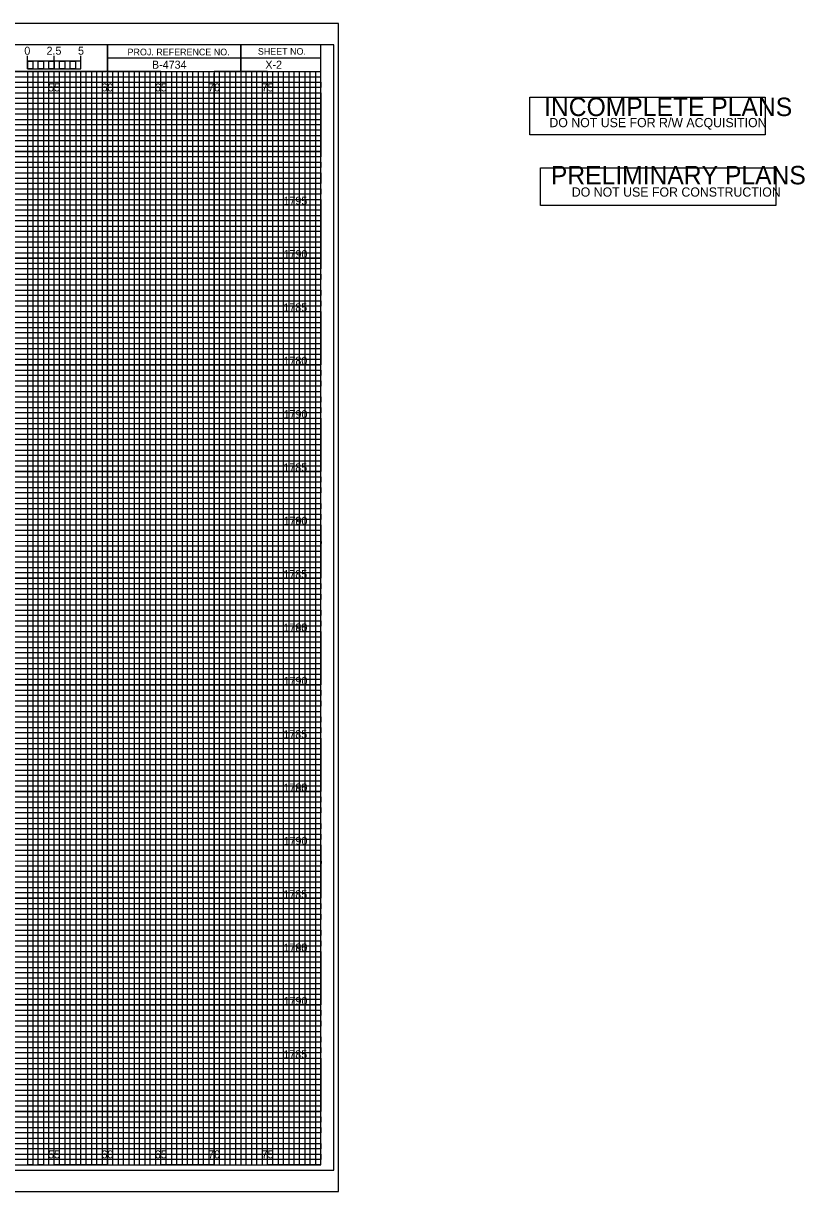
# Model space of a CAD drawing. Extents: x -7 to 205, y -2 to 107.
# Drawn here: x 132.1 to 205.3, y -2.5 to 107 of the extents above; entities that cross this region are included whole.
import ezdxf

# ---------------------------------------------------------------- set-up
doc = ezdxf.new("R2010")
doc.units = 0
for name, color, linetype in [('Prop XS Bar Scale Labels', 7, 'Continuous'), ('Prop XS Elevation Labels', 7, 'Continuous'), ('Prop XS Offset Labels', 7, 'Continuous'), ('Prop XS Project Number', 7, 'Continuous'), ('Prop XS Sheet Number', 7, 'Continuous'), ('Sheet Cross Section CELL', 7, 'Continuous'), ('Sheet Cross Section Grid Major CELL', 7, 'Continuous'), ('Sheet Cross Section Grid Middle CELL', 7, 'Continuous'), ('Sheet Cross Section Grid Minor 1 CELL', 7, 'Continuous'), ('Sheet Cross Section Grid Minor 2 CELL', 7, 'Continuous'), ('Sheet Cross Section Scale CELL', 7, 'Continuous'), ('Sheet Cutting Line CELL', 7, 'Continuous'), ('Sheet DOT Grid CELL', 7, 'Continuous'), ('Sheet Plot Border Inside CELL', 7, 'Continuous'), ('Sheet Plot Border Outside CELL', 7, 'Continuous'), ('Sheet Sticker Incomplete CELL', 7, 'Continuous'), ('Sheet Sticker Preliminary CELL', 7, 'Continuous')]:
    doc.layers.add(name, color=color, linetype=linetype)

msp = doc.modelspace()

# ---------------------------------------------------------------- linework, layer by layer
at = {"layer": 'Sheet Cross Section CELL'}
for p, q in [((152.5, 105), (152.5, 102.5)), ((152.5, 102.5), (152.5, 105)), ((160, 103.75), (140, 103.75)), ((140, 103.75), (140, 102.5)), ((140, 102.5), (160, 102.5))]:
    msp.add_line(p, q, dxfattribs=at)
for points in [[(160, 105), (0, 105), (0, 0), (160, 0)], [(140, 105), (130, 105), (130, 102.52), (140, 102.52)], [(160, 105), (140, 105), (140, 102.5), (160, 102.5)]]:
    msp.add_lwpolyline(points, close=True, dxfattribs=at)
at = {"layer": 'Sheet Cross Section Grid Major CELL'}
for p, q in [((135, 0), (135, 102.5)), ((145, 102.5), (140, 102.5)), ((140, 102.5), (140, 0)), ((145, 0), (145, 102.5)), ((155, 102.5), (150, 102.5)), ((150, 102.5), (150, 0)), ((155, 0), (155, 102.5)), ((140, 0), (135, 0)), ((150, 0), (145, 0)), ((160, 0), (155, 0)), ((160, 0), (160, 0))]:
    msp.add_line(p, q, dxfattribs=at)
for points in [[(0, 100), (160, 100), (160, 95), (0, 95)], [(0, 90), (160, 90), (160, 85), (0, 85)], [(0, 80), (160, 80), (160, 75), (0, 75)], [(0, 70), (160, 70), (160, 65), (0, 65)], [(0, 60), (160, 60), (160, 55), (0, 55)], [(0, 50), (160, 50), (160, 45), (0, 45)], [(0, 40), (160, 40), (160, 35), (0, 35)], [(0, 30), (160, 30), (160, 25), (0, 25)], [(0, 20), (160, 20), (160, 15), (0, 15)], [(0, 10), (160, 10), (160, 5), (0, 5)]]:
    msp.add_lwpolyline(points, dxfattribs=at)
at = {"layer": 'Sheet Cross Section Grid Middle CELL'}
for points in [[(0, 102.5), (137.5, 102.5)], [(130, 102.5), (132.5, 102.5), (132.5, 0), (137.5, 0), (137.5, 102.5), (142.5, 102.5), (142.5, 0), (147.5, 0), (147.5, 102.5), (152.5, 102.5), (152.5, 0), (157.5, 0), (157.5, 102.5)], [(0, 92.5), (160, 92.5), (160, 97.5), (0, 97.5)], [(0, 82.5), (160, 82.5), (160, 87.5), (0, 87.5)], [(0, 72.5), (160, 72.5), (160, 77.5), (0, 77.5)], [(0, 62.5), (160, 62.5), (160, 67.5), (0, 67.5)], [(0, 52.5), (160, 52.5), (160, 57.5), (0, 57.5)], [(0, 42.5), (160, 42.5), (160, 47.5), (0, 47.5)], [(0, 32.5), (160, 32.5), (160, 37.5), (0, 37.5)], [(0, 22.5), (160, 22.5), (160, 27.5), (0, 27.5)], [(0, 12.5), (160, 12.5), (160, 17.5), (0, 17.5)], [(0, 2.5), (160, 2.5), (160, 7.5), (0, 7.5)]]:
    msp.add_lwpolyline(points, dxfattribs=at)
at = {"layer": 'Sheet Cross Section Grid Minor 1 CELL'}
msp.add_line((0, 102), (160, 102), dxfattribs=at)
for points in [[(0, 101.5), (135, 101.5), (160, 101.5), (160, 101), (0, 101)], [(0, 100.5), (160, 100.5), (160, 99.5), (0, 99.5)], [(0, 99), (160, 99), (160, 98.5), (0, 98.49)], [(0, 98), (160, 98), (160, 97), (0, 97)], [(0, 96.5), (160, 96.5), (160, 96), (0, 96)], [(0, 95.5), (160, 95.5), (160, 94.5), (0, 94.5)], [(0, 94), (160, 94), (160, 93.5), (0, 93.5)], [(0, 93), (160, 93), (160, 92), (0, 92)], [(0, 91.5), (160, 91.5), (160, 91), (0, 91)], [(0, 90.5), (160, 90.5), (160, 89.5), (0, 89.5)], [(0, 89), (160, 89), (160, 88.5), (0, 88.5)], [(0, 88), (160, 88), (160, 86.98), (160, 86.5), (160, 86), (0, 86)], [(0, 87), (160, 87), (160, 86.5), (0, 86.5)], [(0, 85.5), (160, 85.5), (160, 84.5), (0, 84.52)], [(0, 84.52), (160, 84.5), (160, 84), (0, 84)], [(0, 83.5), (160, 83.5), (160, 83), (0, 83)], [(0, 82), (160, 82), (160, 81.5), (0, 81.5)], [(0, 81), (160, 81), (160, 80.5), (0, 80.5)], [(-0.04, 79.45), (160, 79.45), (160, 78.94), (-0.04, 78.94)], [(0, 78.5), (160, 78.5), (160, 78), (0, 78)], [(0, 77), (160, 77), (160, 76.5), (0, 76.5)], [(0, 76), (160, 76), (160, 75.5), (0, 75.5)], [(0, 74.5), (160, 74.5), (160, 74), (0, 74)], [(0, 73.5), (160, 73.5), (160, 73), (0, 73)], [(0, 72), (160, 72), (160, 71.5), (0, 71.5)], [(0, 71), (160, 71), (160, 70.5), (0, 70.5)], [(0, 69.5), (160, 69.5), (160, 68.99), (0, 69)], [(0, 68.5), (160, 68.5), (160, 68), (0, 68)], [(0, 67), (160, 67), (160, 66.5), (0, 66.5)], [(0, 66), (160, 66), (160, 65.5), (0, 65.5)], [(0, 64.5), (160, 64.5), (160, 64), (0, 64)], [(0, 63.5), (160, 63.5), (160, 63), (0, 63)], [(0, 62), (160, 62), (160, 61.5), (0, 61.5)], [(0, 61), (160, 61), (160, 60.5), (0, 60.5)], [(0, 59.5), (160, 59.5), (160, 59), (0, 59)], [(0, 58.5), (160.03, 58.45), (160, 58), (0, 58)], [(0, 57), (160, 57), (160, 56.5), (0, 56.5)], [(0, 56), (160, 56), (160, 55.5), (0, 55.5)], [(0, 54.5), (160, 54.5), (160, 54), (0, 54)], [(0, 53.5), (160, 53.5), (160, 53), (0, 53)], [(0, 52), (160, 52), (160, 51.5), (0, 51.5)], [(0, 51), (160, 51), (160, 50.5), (0, 50.5)], [(0, 49.5), (160, 49.5), (160, 49), (0, 49)], [(0, 48.5), (160, 48.5), (160, 48), (0, 48)], [(0, 47), (160, 47), (160, 46.5), (0, 46.5)], [(0, 46), (160, 46), (160, 45.5), (0, 45.5)], [(0, 44.5), (160, 44.5), (160, 44), (0, 44)], [(0, 43.5), (160, 43.5), (160, 43), (0, 43)], [(0, 42), (160, 42), (160, 41.5), (0, 41.5)], [(0, 41), (160, 41), (160, 40.5), (0, 40.5)], [(0, 39.5), (160, 39.5), (160, 38.99), (0, 39)], [(0, 38.5), (160, 38.5), (160, 38), (0, 38)], [(0, 37), (160, 37), (160, 36.5), (0, 36.5)], [(0, 36), (160, 36), (160, 35.5), (0, 35.5)], [(0, 34.5), (160, 34.5), (160, 34), (0, 34)], [(0, 33.5), (160, 33.5), (160, 33), (0, 33)], [(0, 32), (160, 32), (160, 31.5), (0, 31.5)], [(0, 31), (160, 31), (160, 30.5), (0, 30.5)], [(0, 29.5), (160, 29.5), (160, 29), (0, 29)], [(0, 28.5), (160.03, 28.46), (160, 28), (0, 28)], [(0, 27), (160, 27), (160, 26.5), (0, 26.5)], [(0, 26), (160, 26), (160, 25.5), (0, 25.5)], [(0, 24.5), (160, 24.5), (160, 24), (0, 24)], [(0, 23.5), (160, 23.5), (160, 23), (0, 23)], [(0, 22), (160, 22), (160, 21.5), (0, 21.5)], [(0, 21), (160, 21), (160, 20.5), (0, 20.5)], [(0, 19.5), (160, 19.5), (160, 19), (0, 19)], [(0, 18.5), (160, 18.5), (160, 18), (0, 18)], [(0, 17), (160, 17), (160, 16.5), (0, 16.5)], [(0, 16), (160, 16), (160, 15.5), (0, 15.5)], [(0, 14.5), (160, 14.5), (160, 14), (0, 14)], [(0, 13.5), (160, 13.5), (160, 13), (0, 13)], [(0, 12), (160, 12), (160, 11.5), (0, 11.5)], [(0, 11), (160, 11), (160, 10.5), (0, 10.5)], [(0, 9.5), (160, 9.5), (160, 9), (0, 9)], [(0, 8.5), (160, 8.5), (160, 8), (0, 8)], [(0, 7), (160, 7), (160, 6.5), (0, 6.5)], [(0, 6), (160, 6), (160, 5.5), (0, 5.5)], [(0, 4.5), (160, 4.5), (160, 4), (0, 4)], [(0, 3.5), (160, 3.5), (160, 3), (0, 3)], [(0, 2), (160, 2), (160, 1.5), (0, 1.5)], [(0, 1), (160, 1), (160, 0.5), (0, 0.5)]]:
    msp.add_lwpolyline(points, dxfattribs=at)
at = {"layer": 'Sheet Cross Section Grid Minor 2 CELL'}
for p, q in [((133.5, 102.5), (133, 102.5)), ((133, 102.5), (133, 0)), ((133.5, 0), (133.5, 102.5)), ((134.5, 102.5), (134, 102.5)), ((134, 102.5), (134, 0)), ((134.5, 0), (134.5, 102.5)), ((133, 0), (132.5, 0)), ((134, 0), (133.5, 0))]:
    msp.add_line(p, q, dxfattribs=at)
for points in [[(135, 0), (135.49, 0), (135.49, 102.5), (136, 102.5), (136, 0)], [(136, 0), (136.5, 0), (136.5, 102.5), (137.03, 102.5), (137.03, 0)], [(137.5, 0), (138, 0), (138, 102.5), (138.5, 102.5), (138.5, 0)], [(138.5, 0), (139, 0), (139, 102.5), (139.5, 102.5), (139.5, 0)], [(140, 0), (140.5, 0), (140.5, 102.5), (141, 102.5), (141, 0)], [(141, 0), (141.5, 0), (141.5, 102.5), (142, 102.5), (142, 0)], [(142.5, 0), (143, 0), (143, 102.5), (143.5, 102.5), (143.5, 0)], [(143.5, 0), (144, 0), (144, 102.5), (144.5, 102.5), (144.5, 0)], [(145, 0), (145.5, 0), (145.5, 102.5), (146, 102.5), (146, 0)], [(146, 0), (146.5, 0), (146.5, 102.5), (147, 102.5), (147, 0)], [(147.5, 0), (148, 0), (148, 102.5), (148.5, 102.5), (148.5, 0)], [(148.5, 0), (149, 0), (149, 102.5), (149.5, 102.5), (149.5, 0)], [(150, 0), (150.5, 0), (150.5, 102.5), (151, 102.5), (151, 0)], [(151, 0), (151.5, 0), (151.5, 102.5), (152, 102.5), (152, 0)], [(152.5, 0), (153, 0), (153, 102.5), (153.5, 102.5), (153.5, 0)], [(153.5, 0), (154, 0), (154, 102.5), (154.5, 102.5), (154.5, 0)], [(155, 0), (155.5, 0), (155.5, 102.5), (156, 102.5), (156, 0)], [(156, 0), (156.5, 0), (156.5, 102.5), (157, 102.5), (157, 0)], [(157.5, 0), (158, 0), (158, 102.5), (158.5, 102.5), (158.5, 0)], [(158.5, 0), (159, 0), (159, 102.5), (159.5, 102.5), (159.5, 0)]]:
    msp.add_lwpolyline(points, dxfattribs=at)
at = {"layer": 'Sheet Cross Section Scale CELL'}
for p, q in [((132.5, 102.75), (132.5, 103.95)), ((132.5, 103.45), (132.5, 103.95)), ((135, 102.75), (135, 103.95)), ((137.5, 102.75), (137.5, 103.95)), ((137.5, 103.45), (137.5, 103.95))]:
    msp.add_line(p, q, dxfattribs=at)
for points in [[(137.5, 103.45), (132.5, 103.45), (132.5, 102.75), (137.5, 102.75)], [(132.5, 103.45), (133, 103.45), (133, 102.75), (132.5, 102.75)], [(133.5, 103.45), (134, 103.45), (134, 102.75), (133.5, 102.75)], [(134.5, 103.45), (135, 103.45), (135, 102.75), (134.5, 102.75)], [(135.5, 103.45), (136, 103.45), (136, 102.75), (135.5, 102.75)], [(136.5, 103.45), (137, 103.45), (137, 102.75), (136.5, 102.75)]]:
    msp.add_lwpolyline(points, close=True, dxfattribs=at)
at = {"layer": 'Sheet Cutting Line CELL'}
for p, q in [((161.65, 107), (-6.7, 107)), ((-6.7, -2.5), (161.65, -2.5))]:
    msp.add_line(p, q, dxfattribs=at)
at = {"layer": 'Sheet DOT Grid CELL'}
for p, q in [((135, 0), (135, 102.34)), ((140, 0), (140, 102.34)), ((145, 0), (145, 102.34)), ((150, 0), (150, 102.34)), ((155, 0), (155, 102.34)), ((0, 100), (160, 100)), ((0, 95), (160, 95)), ((0, 90), (160, 90)), ((0, 85), (160, 85)), ((0, 80), (160, 80)), ((0, 75), (160, 75)), ((0, 70), (160, 70)), ((0, 65), (160, 65)), ((0, 60), (160, 60)), ((0, 55), (160, 55)), ((0, 50), (160, 50)), ((0, 45), (160, 45)), ((0, 40), (160, 40)), ((0, 35), (160, 35)), ((0, 30), (160, 30)), ((0, 25), (160, 25)), ((0, 20), (160, 20)), ((0, 15), (160, 15)), ((0, 10), (160, 10)), ((0, 5), (160, 5))]:
    msp.add_line(p, q, dxfattribs=at)
at = {"layer": 'Sheet Plot Border Inside CELL'}
msp.add_lwpolyline([(-5.4, -0.5), (161.2, -0.5), (161.2, 105), (-5.4, 105)], close=True, dxfattribs=at)
at = {"layer": 'Sheet Plot Border Outside CELL'}
msp.add_lwpolyline([(-6.7, -2.5), (161.65, -2.5), (161.65, 107), (-6.7, 107)], close=True, dxfattribs=at)
at = {"layer": 'Sheet Sticker Incomplete CELL'}
msp.add_lwpolyline([(179.57, 96.56), (179.57, 100.08), (201.62, 100.08), (201.62, 96.56)], close=True, dxfattribs=at)
at = {"layer": 'Sheet Sticker Preliminary CELL'}
msp.add_lwpolyline([(180.56, 89.94), (180.56, 93.47), (202.61, 93.47), (202.61, 89.94)], close=True, dxfattribs=at)

# ---------------------------------------------------------------- texts
at = {"layer": 'Prop XS Bar Scale Labels'}
for s, p in [('2.5', (134.29, 104.06)), ('5', (137.24, 104.06))]:
    msp.add_text(s, height=0.75, dxfattribs=at).set_placement(p)
at = {"layer": 'Prop XS Elevation Labels'}
for s, p in [('1795', (156.49, 90)), ('1790', (156.5, 85)), ('1785', (156.48, 80)), ('1780', (156.49, 75)), ('1790', (156.5, 70)), ('1785', (156.48, 65)), ('1780', (156.49, 60)), ('1790', (156.5, 60)), ('1785', (156.48, 55)), ('1795', (156.49, 50)), ('1780', (156.49, 50)), ('1790', (156.5, 45)), ('1785', (156.48, 40)), ('1795', (156.49, 35)), ('1780', (156.49, 35)), ('1790', (156.5, 30)), ('1785', (156.48, 25)), ('1795', (156.49, 20)), ('1780', (156.49, 20)), ('1790', (156.5, 15)), ('1785', (156.48, 10))]:
    msp.add_text(s, height=0.75, dxfattribs=at).set_placement(p)
at = {"layer": 'Prop XS Offset Labels'}
for s, p in [('55', (134.44, 100.62)), ('60', (139.43, 100.62)), ('65', (144.44, 100.62)), ('70', (149.43, 100.62)), ('75', (154.44, 100.62)), ('55', (134.44, 0.62)), ('60', (139.43, 0.62)), ('65', (144.44, 0.62)), ('70', (149.43, 0.62)), ('75', (154.44, 0.62))]:
    msp.add_text(s, height=0.75, dxfattribs=at).set_placement(p)
at = {"layer": 'Prop XS Project Number'}
msp.add_text('B-4734', height=0.75, dxfattribs=at).set_placement((144.17, 102.75))
at = {"layer": 'Prop XS Sheet Number'}
msp.add_text('X-2', height=0.75, dxfattribs=at).set_placement((154.79, 102.75))
at = {"layer": 'Sheet Cross Section CELL'}
for s, p in [('PROJ. REFERENCE NO.', (141.88, 104)), ('SHEET NO.', (154.09, 104.06))]:
    msp.add_text(s, height=0.625, dxfattribs=at).set_placement(p)
at = {"layer": 'Sheet Cross Section Scale CELL'}
msp.add_text('0', height=0.75, dxfattribs=at).set_placement((132.21, 104.06))
at = {"layer": 'Sheet Sticker Incomplete CELL'}
for s, height, p in [('INCOMPLETE PLANS', 1.728, (180.91, 98.31)), ('DO NOT USE FOR R/W ACQUISITION', 0.864, (181.4, 97.27))]:
    msp.add_text(s, height=height, dxfattribs=at).set_placement(p)
at = {"layer": 'Sheet Sticker Preliminary CELL'}
for s, height, p in [('PRELIMINARY PLANS', 1.728, (181.54, 91.91)), ('DO NOT USE FOR CONSTRUCTION', 0.864, (183.5, 90.76))]:
    msp.add_text(s, height=height, dxfattribs=at).set_placement(p)

doc.saveas('drawing.dxf')
